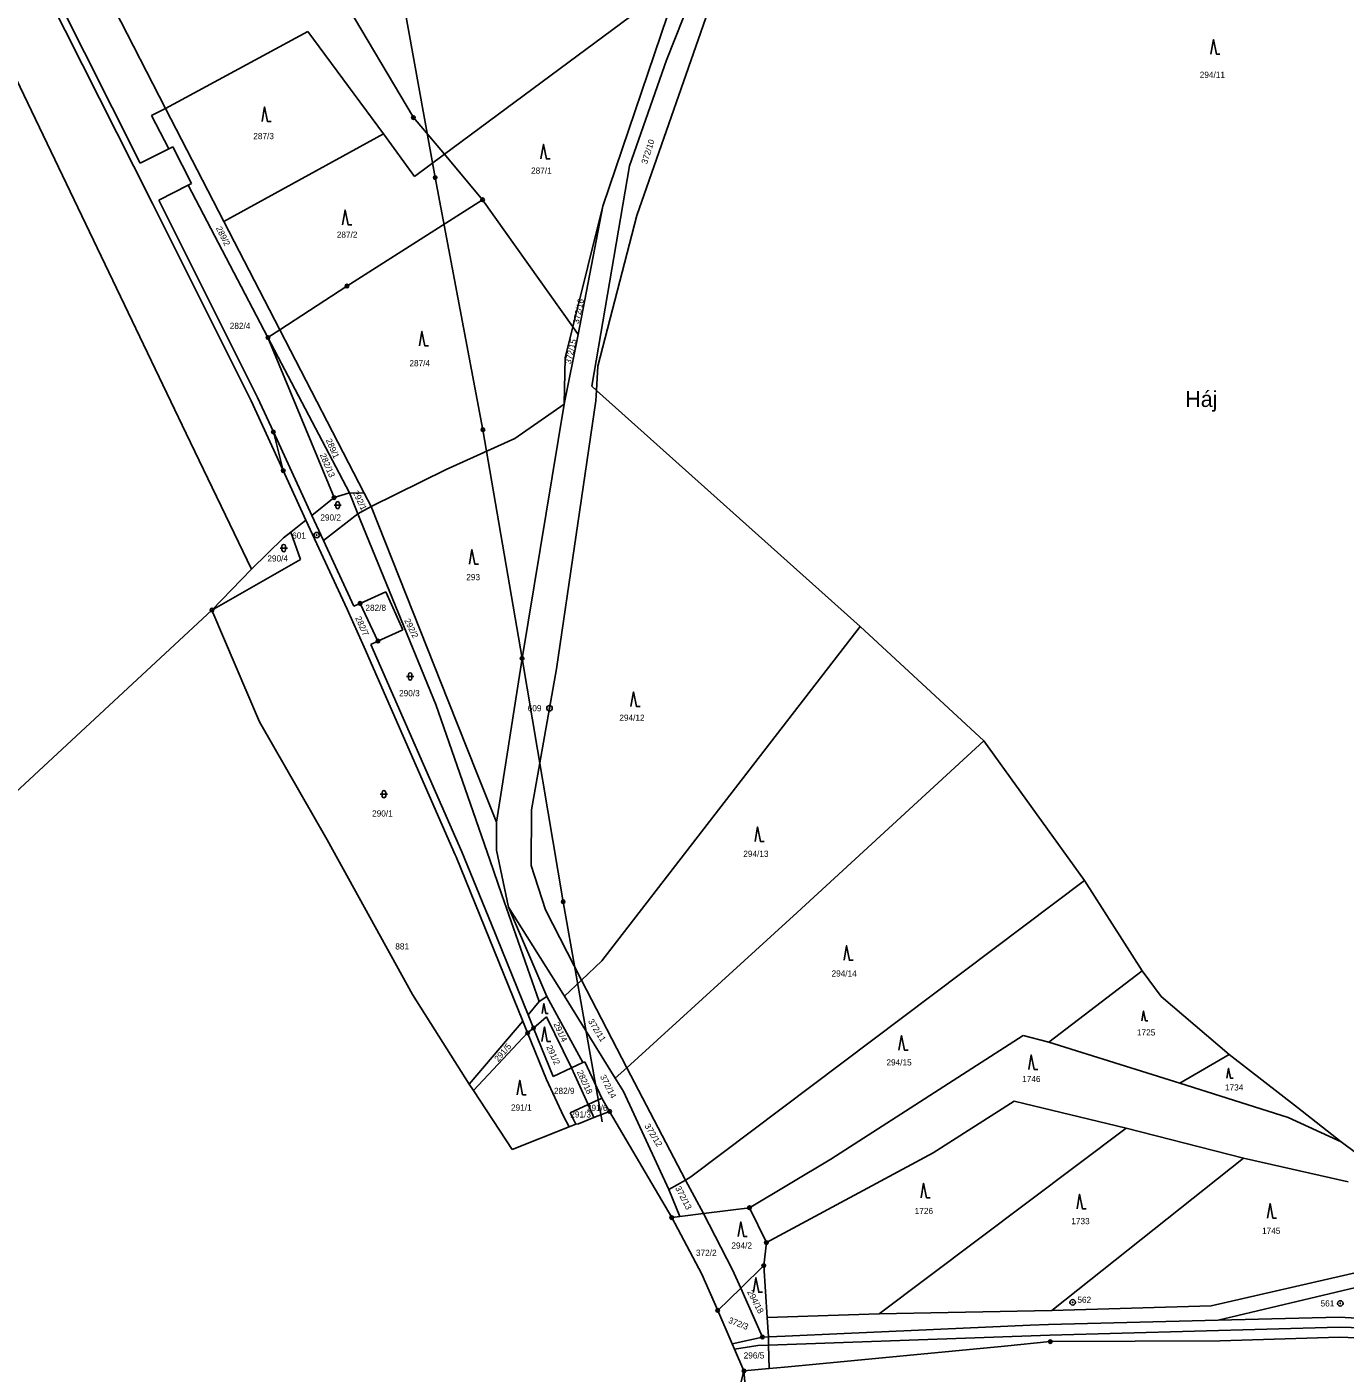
# Model space of a CAD drawing. Extents: x -762263 to -760336, y -1154405 to -1152076.
# Drawn here: x -761653.2 to -761289.6, y -1153689.1 to -1153317.8 of the extents above; entities that cross this region are included whole.
import ezdxf

# ---------------------------------------------------------------- set-up
doc = ezdxf.new("R2010")
doc.units = 0
for name, color, linetype in [('Vrstva 1', 7, 'Continuous'), ('Vrstva 10', 7, 'Continuous'), ('Vrstva 12', 7, 'Continuous'), ('Vrstva 13', 7, 'Continuous'), ('Vrstva 15', 7, 'Continuous'), ('Vrstva 17', 7, 'Continuous'), ('Vrstva 18', 7, 'Continuous'), ('Vrstva 24', 7, 'Continuous'), ('Vrstva 25', 7, 'Continuous'), ('Vrstva 26', 7, 'Continuous'), ('Vrstva 6', 7, 'Continuous')]:
    doc.layers.add(name, color=color, linetype=linetype)

msp = doc.modelspace()

# ---------------------------------------------------------------- linework, layer by layer
at = {"layer": 'Vrstva 1'}
for p, q in [((-761546.59, -1153342.78), (-761585.96, -1153276.37)), ((-761671.74, -1153299.75), (-761609.26, -1153429.89)), ((-761623.76, -1153356.3), (-761651.47, -1153301.16)), ((-761649.68, -1153300.26), (-761621.98, -1153355.4)), ((-761615.01, -1153340.25), (-761634.02, -1153303.16)), ((-761538.06, -1153352.92), (-761473.17, -1153304.68)), ((-761473.17, -1153304.68), (-761494.36, -1153367.21)), ((-761463.8, -1153309.13), (-761484.99, -1153369.81)), ((-761615.01, -1153340.25), (-761575.68, -1153319.01)), ((-761575.68, -1153319.01), (-761554.88, -1153347.32)), ((-761615.01, -1153340.25), (-761618.84, -1153342.23)), ((-761598.9, -1153371.41), (-761615.01, -1153340.25)), ((-761618.84, -1153342.23), (-761614.04, -1153351.37)), ((-761546.59, -1153342.78), (-761538.06, -1153352.92)), ((-761554.88, -1153347.32), (-761598.9, -1153371.41)), ((-761554.88, -1153347.32), (-761546.28, -1153359.03)), ((-761621.98, -1153355.4), (-761614.04, -1153351.37)), ((-761614.04, -1153351.37), (-761612.97, -1153350.83)), ((-761612.97, -1153350.83), (-761607.81, -1153361)), ((-761546.28, -1153359.03), (-761538.06, -1153352.92)), ((-761527.52, -1153365.45), (-761538.06, -1153352.92)), ((-761618.61, -1153366.47), (-761623.76, -1153356.3)), ((-761608.74, -1153361.47), (-761616.82, -1153365.57)), ((-761607.81, -1153361), (-761608.74, -1153361.47)), ((-761608.74, -1153361.47), (-761586.71, -1153403.45)), ((-761616.82, -1153365.57), (-761589.59, -1153420.02)), ((-761527.52, -1153365.45), (-761564.95, -1153389.27)), ((-761591.38, -1153420.92), (-761618.61, -1153366.47)), ((-761502.61, -1153400.49), (-761494.36, -1153367.21)), ((-761484.99, -1153369.81), (-761495.74, -1153411.4)), ((-761583.44, -1153401.32), (-761598.9, -1153371.41)), ((-761564.95, -1153389.27), (-761583.44, -1153401.32)), ((-761583.44, -1153401.32), (-761586.71, -1153403.45)), ((-761586.71, -1153403.45), (-761568.46, -1153447.6)), ((-761586.71, -1153403.45), (-761564.19, -1153446.25)), ((-761560.14, -1153446.41), (-761583.44, -1153401.32)), ((-761504.73, -1153409.05), (-761502.61, -1153400.49)), ((-761504.73, -1153409.05), (-761504.96, -1153421.81)), ((-761495.74, -1153411.4), (-761496.11, -1153418.05)), ((-761496.11, -1153418.05), (-761496.27, -1153420.93)), ((-761582.51, -1153440.17), (-761591.38, -1153420.92)), ((-761589.59, -1153420.02), (-761585.22, -1153429.51)), ((-761504.96, -1153421.81), (-761518.6, -1153431.34)), ((-761504.96, -1153421.81), (-761516.6, -1153491.95)), ((-761496.27, -1153420.93), (-761507.12, -1153494.8)), ((-761585.22, -1153429.51), (-761582.51, -1153440.17)), ((-761574.62, -1153452.51), (-761585.22, -1153429.51)), ((-761609.26, -1153429.89), (-761591.28, -1153467.34)), ((-761537.59, -1153439.84), (-761518.6, -1153431.34)), ((-761576.23, -1153453.8), (-761582.51, -1153440.17)), ((-761558.26, -1153450.05), (-761537.59, -1153439.84)), ((-761568.46, -1153447.6), (-761574.62, -1153452.51)), ((-761568.46, -1153447.6), (-761564.19, -1153446.25)), ((-761560.14, -1153446.41), (-761564.19, -1153446.25)), ((-761564.19, -1153446.25), (-761561.91, -1153452.09)), ((-761558.26, -1153450.05), (-761560.14, -1153446.41)), ((-761536.98, -1153503.67), (-761558.26, -1153450.05)), ((-761580.38, -1153457.11), (-761576.23, -1153453.8)), ((-761564.89, -1153478.4), (-761576.23, -1153453.8)), ((-761571.44, -1153459.41), (-761574.62, -1153452.51)), ((-761561.91, -1153452.09), (-761561.2, -1153453.92)), ((-761561.2, -1153453.92), (-761540.45, -1153504.69)), ((-761591.28, -1153467.34), (-761582.39, -1153458.71)), ((-761582.39, -1153458.71), (-761580.38, -1153457.11)), ((-761563.07, -1153477.59), (-761571.44, -1153459.41)), ((-761591.28, -1153467.34), (-761602.19, -1153478.64)), ((-761554.21, -1153473.62), (-761561.31, -1153476.8)), ((-761549.51, -1153484.11), (-761554.21, -1153473.62)), ((-761563.07, -1153477.59), (-761561.31, -1153476.8)), ((-761561.31, -1153476.8), (-761556.38, -1153487.19)), ((-761560.19, -1153488.9), (-761564.89, -1153478.4)), ((-761556.38, -1153487.19), (-761549.51, -1153484.11)), ((-761560.19, -1153488.9), (-761535.03, -1153546.15)), ((-761556.38, -1153487.19), (-761558.36, -1153488.08)), ((-761558.36, -1153488.08), (-761533.2, -1153545.34)), ((-761523.68, -1153537.15), (-761516.6, -1153491.95)), ((-761514.01, -1153533.68), (-761507.12, -1153494.8)), ((-761536.98, -1153503.67), (-761528.98, -1153523.8)), ((-761540.45, -1153504.69), (-761530.88, -1153532.15)), ((-761528.98, -1153523.8), (-761523.68, -1153537.15)), ((-761530.88, -1153532.15), (-761525.53, -1153547.5)), ((-761523.68, -1153537.15), (-761523.7, -1153544.89)), ((-761514.11, -1153549.12), (-761514.01, -1153533.68)), ((-761535.03, -1153546.15), (-761534.83, -1153546.64)), ((-761534.83, -1153546.64), (-761516.39, -1153592.04)), ((-761525.18, -1153565.08), (-761533.2, -1153545.34)), ((-761525.53, -1153547.5), (-761522.16, -1153557.16)), ((-761520.35, -1153560.57), (-761523.7, -1153544.89)), ((-761510.2, -1153561.34), (-761514.11, -1153549.12)), ((-761522.16, -1153557.16), (-761511.91, -1153586.55)), ((-761509.76, -1153585.2), (-761520.35, -1153560.57)), ((-761510.2, -1153561.34), (-761500.2, -1153580.68)), ((-761514.93, -1153590.3), (-761525.18, -1153565.08)), ((-761500.2, -1153580.68), (-761487.71, -1153604.85)), ((-761511.91, -1153586.55), (-761509.76, -1153585.2)), ((-761509.76, -1153585.2), (-761499.82, -1153603.44)), ((-761514.93, -1153590.3), (-761511.91, -1153586.55)), ((-761531.17, -1153609.36), (-761516.39, -1153592.04)), ((-761515.08, -1153595.26), (-761516.39, -1153592.04)), ((-761513.46, -1153593.93), (-761514.93, -1153590.3)), ((-761515.08, -1153595.26), (-761513.46, -1153593.93)), ((-761515.08, -1153595.26), (-761509.86, -1153608.11)), ((-761513.46, -1153593.93), (-761508.04, -1153607.27)), ((-761502.98, -1153604.91), (-761499.82, -1153603.44)), ((-761499.82, -1153603.44), (-761499.34, -1153603.22)), ((-761494.66, -1153613.28), (-761499.34, -1153603.22)), ((-761508.04, -1153607.27), (-761502.98, -1153604.91)), ((-761487.71, -1153604.85), (-761471.51, -1153635.83)), ((-761509.86, -1153608.11), (-761505.18, -1153618.17)), ((-761503.36, -1153617.33), (-761498.42, -1153615.03)), ((-761498.42, -1153615.03), (-761494.66, -1153613.28)), ((-761494.66, -1153613.28), (-761492.48, -1153616.91)), ((-761505.18, -1153618.17), (-761503.66, -1153621.12)), ((-761501.77, -1153620.41), (-761503.36, -1153617.33)), ((-761471.51, -1153635.83), (-761466.61, -1153645.08)), ((-761453.91, -1153643.47), (-761466.61, -1153645.08)), ((-761449.22, -1153653.1), (-761453.91, -1153643.47)), ((-761473.07, -1153645.89), (-761475.33, -1153646.18)), ((-761466.61, -1153645.08), (-761473.07, -1153645.89)), ((-761466.61, -1153645.08), (-761458.55, -1153660.55)), ((-761449.94, -1153659.44), (-761449.22, -1153653.1)), ((-761456.3, -1153665.62), (-761449.94, -1153659.44)), ((-761456.3, -1153665.62), (-761458.55, -1153660.55)), ((-761462.66, -1153671.8), (-761456.3, -1153665.62)), ((-761456.3, -1153665.62), (-761450.3, -1153679.16)), ((-761371.36, -1153675.66), (-761324.64, -1153674.46)), ((-761324.64, -1153674.46), (-761291.26, -1153673.61)), ((-761291.26, -1153673.61), (-761275.44, -1153674.5)), ((-761427.75, -1153678.16), (-761444.01, -1153678.88)), ((-761376.47, -1153675.89), (-761427.75, -1153678.16)), ((-761371.36, -1153675.66), (-761376.47, -1153675.89)), ((-761450.3, -1153679.16), (-761458.67, -1153680.99)), ((-761448.66, -1153679.09), (-761450.3, -1153679.16)), ((-761444.01, -1153678.88), (-761448.66, -1153679.09)), ((-761448.66, -1153679.09), (-761448.61, -1153681.37)), ((-761448.61, -1153681.37), (-761448.46, -1153687.82)), ((-761439.34, -1153686.94), (-761383.57, -1153681.61)), ((-761383.57, -1153681.61), (-761370.9, -1153680.4)), ((-761324.05, -1153680.22), (-761370.9, -1153680.4)), ((-761291.2, -1153679.17), (-761324.05, -1153680.22)), ((-761291.2, -1153679.17), (-761277.28, -1153679.74)), ((-761448.46, -1153687.82), (-761455.41, -1153688.48)), ((-761455.41, -1153688.48), (-761454.42, -1153699.45)), ((-761448.46, -1153687.82), (-761444.27, -1153687.41)), ((-761444.27, -1153687.41), (-761439.34, -1153686.94))]:
    msp.add_line(p, q, dxfattribs=at)
at = {"layer": 'Vrstva 10'}
for p, q in [((-761291.23, -1153676.37), (-761371.07, -1153678.63)), ((-761276.25, -1153676.81), (-761291.23, -1153676.37)), ((-761451.57, -1153681.47), (-761458.03, -1153682.46)), ((-761448.61, -1153681.37), (-761451.57, -1153681.47)), ((-761371.07, -1153678.63), (-761448.61, -1153681.37))]:
    msp.add_line(p, q, dxfattribs=at)
at = {"layer": 'Vrstva 12'}
for p, q in [((-761540.59, -1153359.34), (-761554.96, -1153280.07)), ((-761527.43, -1153428.89), (-761540.59, -1153359.34)), ((-761516.6, -1153491.95), (-761527.43, -1153428.89)), ((-761505.28, -1153559.08), (-761516.6, -1153491.95)), ((-761505.28, -1153559.08), (-761494.49, -1153619.73))]:
    msp.add_line(p, q, dxfattribs=at)
at = {"layer": 'Vrstva 13'}
for p, q in [((-761784.65, -1153648.01), (-761602.19, -1153478.64)), ((-761602.19, -1153478.64), (-761589.02, -1153509.45)), ((-761589.02, -1153509.45), (-761570.39, -1153541.98)), ((-761570.39, -1153541.98), (-761546.8, -1153584.66)), ((-761546.8, -1153584.66), (-761531.17, -1153609.36)), ((-761531.17, -1153609.36), (-761530.02, -1153611.11)), ((-761530.02, -1153611.11), (-761519.36, -1153627.45)), ((-761501.09, -1153620.29), (-761496.81, -1153618.61)), ((-761496.81, -1153618.61), (-761492.48, -1153616.91)), ((-761492.48, -1153616.91), (-761475.33, -1153646.18)), ((-761519.36, -1153627.45), (-761503.66, -1153621.12)), ((-761503.66, -1153621.12), (-761501.77, -1153620.41)), ((-761501.77, -1153620.41), (-761501.09, -1153620.29)), ((-761475.33, -1153646.18), (-761467.02, -1153661.75)), ((-761467.02, -1153661.75), (-761462.66, -1153671.8)), ((-761462.66, -1153671.8), (-761458.67, -1153680.99)), ((-761458.67, -1153680.99), (-761458.03, -1153682.46)), ((-761458.03, -1153682.46), (-761455.41, -1153688.48)), ((-761458.47, -1153700.93), (-761455.41, -1153688.48))]:
    msp.add_line(p, q, dxfattribs=at)
at = {"layer": 'Vrstva 24'}
for centre, radius in [((-761546.59, -1153342.78), 0.5), ((-761546.59, -1153342.78), 0.1), ((-761527.52, -1153365.45), 0.5), ((-761527.52, -1153365.45), 0.1), ((-761564.95, -1153389.27), 0.5), ((-761564.95, -1153389.27), 0.1), ((-761586.71, -1153403.45), 0.5), ((-761586.71, -1153403.45), 0.1), ((-761585.22, -1153429.51), 0.5), ((-761585.22, -1153429.51), 0.1), ((-761582.51, -1153440.17), 0.5), ((-761582.51, -1153440.17), 0.1), ((-761568.46, -1153447.6), 0.5), ((-761568.46, -1153447.6), 0.1), ((-761573.27, -1153457.95), 0.75), ((-761573.27, -1153457.95), 0.1), ((-761561.31, -1153476.8), 0.5), ((-761561.31, -1153476.8), 0.1), ((-761602.19, -1153478.64), 0.5), ((-761602.19, -1153478.64), 0.1), ((-761556.38, -1153487.19), 0.5), ((-761556.38, -1153487.19), 0.1), ((-761509.05, -1153505.69), 0.75), ((-761509.05, -1153505.69), 0.1), ((-761515.08, -1153595.26), 0.5), ((-761515.08, -1153595.26), 0.1), ((-761513.46, -1153593.93), 0.5), ((-761513.46, -1153593.93), 0.1), ((-761492.48, -1153616.91), 0.5), ((-761492.48, -1153616.91), 0.1), ((-761453.91, -1153643.47), 0.5), ((-761453.91, -1153643.47), 0.1), ((-761475.33, -1153646.18), 0.5), ((-761475.33, -1153646.18), 0.1), ((-761449.22, -1153653.1), 0.5), ((-761449.22, -1153653.1), 0.1), ((-761449.94, -1153659.44), 0.5), ((-761449.94, -1153659.44), 0.1), ((-761364.72, -1153669.57), 0.75), ((-761364.72, -1153669.57), 0.1), ((-761290.9, -1153669.85), 0.75), ((-761290.9, -1153669.85), 0.1), ((-761462.66, -1153671.8), 0.5), ((-761462.66, -1153671.8), 0.1), ((-761450.3, -1153679.16), 0.5), ((-761450.3, -1153679.16), 0.1), ((-761370.9, -1153680.4), 0.5), ((-761370.9, -1153680.4), 0.1), ((-761455.41, -1153688.48), 0.5), ((-761455.41, -1153688.48), 0.1)]:
    msp.add_circle(centre, radius, dxfattribs=at)
at = {"layer": 'Vrstva 25'}
for p, q in [((-761568.48, -1153449.69), (-761566.48, -1153449.69)), ((-761567.98, -1153450.19), (-761567.98, -1153449.19)), ((-761566.98, -1153449.19), (-761566.98, -1153450.19)), ((-761583.36, -1153461.53), (-761581.36, -1153461.53)), ((-761582.86, -1153462.03), (-761582.86, -1153461.03)), ((-761581.86, -1153461.03), (-761581.86, -1153462.03)), ((-761548.49, -1153496.92), (-761546.49, -1153496.92)), ((-761547.99, -1153497.42), (-761547.99, -1153496.42)), ((-761546.99, -1153496.42), (-761546.99, -1153497.42)), ((-761555.72, -1153529.41), (-761553.72, -1153529.41)), ((-761555.22, -1153529.91), (-761555.22, -1153528.91)), ((-761554.22, -1153528.91), (-761554.22, -1153529.91))]:
    msp.add_line(p, q, dxfattribs=at)
for points in [[(-761326.6, -1153325.27), (-761325.9, -1153321.27), (-761325.1, -1153325.27), (-761324.1, -1153325.27)], [(-761588.35, -1153343.83), (-761587.65, -1153339.83), (-761586.85, -1153343.83), (-761585.85, -1153343.83)], [(-761511.4, -1153354.2), (-761510.7, -1153350.2), (-761509.9, -1153354.2), (-761508.9, -1153354.2)], [(-761566.12, -1153372.33), (-761565.42, -1153368.33), (-761564.62, -1153372.33), (-761563.62, -1153372.33)], [(-761544.93, -1153405.78), (-761544.23, -1153401.78), (-761543.43, -1153405.78), (-761542.43, -1153405.78)], [(-761531.15, -1153465.95), (-761530.45, -1153461.95), (-761529.65, -1153465.95), (-761528.65, -1153465.95)], [(-761486.57, -1153505.22), (-761485.87, -1153501.22), (-761485.07, -1153505.22), (-761484.07, -1153505.22)], [(-761452.36, -1153542.44), (-761451.66, -1153538.44), (-761450.86, -1153542.44), (-761449.86, -1153542.44)], [(-761427.81, -1153575.22), (-761427.11, -1153571.22), (-761426.31, -1153575.22), (-761425.31, -1153575.22)], [(-761511.069, -1153589.85), (-761510.6, -1153587.17), (-761510.064, -1153589.85), (-761509.394, -1153589.85)], [(-761345.639, -1153591.9), (-761345.17, -1153589.22), (-761344.634, -1153591.9), (-761343.964, -1153591.9)], [(-761511.17, -1153597.61), (-761510.47, -1153593.61), (-761509.67, -1153597.61), (-761508.67, -1153597.61)], [(-761412.64, -1153599.98), (-761411.94, -1153595.98), (-761411.14, -1153599.98), (-761410.14, -1153599.98)], [(-761376.85, -1153605.32), (-761376.15, -1153601.32), (-761375.35, -1153605.32), (-761374.35, -1153605.32)], [(-761322.169, -1153607.74), (-761321.7, -1153605.06), (-761321.164, -1153607.74), (-761320.494, -1153607.74)], [(-761517.98, -1153612.3), (-761517.28, -1153608.3), (-761516.48, -1153612.3), (-761515.48, -1153612.3)], [(-761406.54, -1153640.72), (-761405.84, -1153636.72), (-761405.04, -1153640.72), (-761404.04, -1153640.72)], [(-761363.52, -1153643.75), (-761362.82, -1153639.75), (-761362.02, -1153643.75), (-761361.02, -1153643.75)], [(-761310.99, -1153646.3), (-761310.29, -1153642.3), (-761309.49, -1153646.3), (-761308.49, -1153646.3)], [(-761456.98, -1153651.36), (-761456.28, -1153647.36), (-761455.48, -1153651.36), (-761454.48, -1153651.36)], [(-761452.82, -1153666.77), (-761452.12, -1153662.77), (-761451.32, -1153666.77), (-761450.32, -1153666.77)]]:
    msp.add_lwpolyline(points, dxfattribs=at)
for centre, start, end in [((-761567.48, -1153449.19), 0, 180), ((-761567.48, -1153450.19), 180, 0), ((-761582.36, -1153461.03), 0, 180), ((-761582.36, -1153462.03), 180, 0), ((-761547.49, -1153496.42), 0, 180), ((-761547.49, -1153497.42), 180, 0), ((-761554.72, -1153528.91), 0, 180), ((-761554.72, -1153529.91), 180, 0)]:
    msp.add_arc(centre, 0.5, start, end, dxfattribs=at)
at = {"layer": 'Vrstva 26'}
for centre in [(-761540.59, -1153359.34), (-761527.43, -1153428.89), (-761516.6, -1153491.95), (-761505.28, -1153559.08)]:
    msp.add_circle(centre, 0.5, dxfattribs=at)
at = {"layer": 'Vrstva 6'}
for p, q in [((-761454.55, -1153270.14), (-761476.76, -1153326.98)), ((-761476.76, -1153326.98), (-761486.97, -1153356.08)), ((-761486.97, -1153356.08), (-761497.41, -1153416.9)), ((-761527.52, -1153365.45), (-761502.61, -1153400.49)), ((-761501.11, -1153402.6), (-761494.36, -1153367.21)), ((-761504.96, -1153421.81), (-761501.11, -1153402.6)), ((-761502.61, -1153400.49), (-761501.11, -1153402.6)), ((-761497.41, -1153416.9), (-761496.11, -1153418.05)), ((-761496.11, -1153418.05), (-761423.33, -1153483.2)), ((-761558.26, -1153450.05), (-761561.91, -1153452.09)), ((-761561.91, -1153452.09), (-761571.44, -1153459.41)), ((-761577.72, -1153464.7), (-761580.38, -1153457.11)), ((-761602.19, -1153478.64), (-761577.72, -1153464.7)), ((-761423.33, -1153483.2), (-761494.6, -1153575.41)), ((-761423.33, -1153483.2), (-761389.25, -1153514.7)), ((-761440.72, -1153562.07), (-761389.25, -1153514.7)), ((-761389.25, -1153514.7), (-761361.48, -1153553.17)), ((-761361.48, -1153553.17), (-761470.06, -1153634.97)), ((-761345.6, -1153578.17), (-761361.48, -1153553.17)), ((-761520.35, -1153560.57), (-761504.92, -1153585.11)), ((-761487.71, -1153604.85), (-761440.72, -1153562.07)), ((-761500.2, -1153580.68), (-761494.6, -1153575.41)), ((-761504.92, -1153585.11), (-761500.2, -1153580.68)), ((-761371.27, -1153597.84), (-761345.6, -1153578.17)), ((-761345.6, -1153578.17), (-761340.33, -1153585.2)), ((-761504.92, -1153585.11), (-761490.9, -1153607.7)), ((-761321.57, -1153601.24), (-761340.33, -1153585.2)), ((-761509.84, -1153590.84), (-761513.46, -1153593.93)), ((-761509.84, -1153590.84), (-761502.98, -1153604.91)), ((-761530.02, -1153611.11), (-761515.08, -1153595.26)), ((-761431.4, -1153630.03), (-761378.43, -1153595.99)), ((-761378.43, -1153595.99), (-761371.27, -1153597.84)), ((-761371.27, -1153597.84), (-761335.2, -1153609.08)), ((-761335.2, -1153609.08), (-761321.57, -1153601.24)), ((-761321.57, -1153601.24), (-761302.69, -1153615.85)), ((-761502.98, -1153604.91), (-761498.42, -1153615.03)), ((-761490.9, -1153607.7), (-761487.71, -1153604.85)), ((-761490.9, -1153607.7), (-761488.65, -1153611.4)), ((-761488.65, -1153611.4), (-761476.1, -1153638.45)), ((-761335.2, -1153609.08), (-761305.31, -1153618.62)), ((-761498.42, -1153615.03), (-761496.81, -1153618.61)), ((-761403.24, -1153628.3), (-761380.87, -1153614.08)), ((-761380.87, -1153614.08), (-761349.98, -1153621.56)), ((-761305.31, -1153618.62), (-761290.69, -1153625.31)), ((-761302.69, -1153615.85), (-761290.69, -1153625.31)), ((-761418.13, -1153672.7), (-761349.98, -1153621.56)), ((-761349.98, -1153621.56), (-761317.63, -1153629.8)), ((-761290.69, -1153625.31), (-761282.41, -1153631.47)), ((-761453.91, -1153643.47), (-761431.4, -1153630.03)), ((-761449.22, -1153653.1), (-761403.24, -1153628.3)), ((-761370.5, -1153671.81), (-761317.63, -1153629.8)), ((-761317.63, -1153629.8), (-761288.72, -1153636.31)), ((-761471.51, -1153635.83), (-761476.1, -1153638.45)), ((-761470.06, -1153634.97), (-761471.51, -1153635.83)), ((-761476.1, -1153638.45), (-761473.07, -1153645.89)), ((-761449.94, -1153659.44), (-761449.01, -1153673.74)), ((-761326.5, -1153670.48), (-761266.86, -1153656.88)), ((-761324.64, -1153674.46), (-761263.67, -1153660)), ((-761370.5, -1153671.81), (-761326.5, -1153670.48)), ((-761449.01, -1153673.74), (-761418.13, -1153672.7)), ((-761449.01, -1153673.74), (-761448.66, -1153679.09)), ((-761418.13, -1153672.7), (-761370.5, -1153671.81))]:
    msp.add_line(p, q, dxfattribs=at)

# ---------------------------------------------------------------- texts
at = {"layer": 'Vrstva 15'}
msp.add_text('Háj', height=4.4, dxfattribs=at).set_placement((-761333.642, -1153422.61))
at = {"layer": 'Vrstva 17'}
for s, p in [('601', (-761580.033, -1153458.92)), ('609', (-761515.058, -1153506.54)), ('881', (-761551.592, -1153572.24)), ('562', (-761363.427, -1153669.7)), ('561', (-761296.346, -1153670.7))]:
    msp.add_text(s, height=1.7, dxfattribs=at).set_placement(p)
at = {"layer": 'Vrstva 18'}
for s, p in [('294/11', (-761329.67, -1153331.84)), ('287/3', (-761590.763, -1153348.75)), ('287/1', (-761514.135, -1153358.27)), ('287/2', (-761567.733, -1153375.94)), ('282/4', (-761597.253, -1153401.09)), ('287/4', (-761547.693, -1153411.4)), ('290/2', (-761572.257, -1153453.94)), ('290/4', (-761586.874, -1153465.23)), ('293', (-761532.003, -1153470.39)), ('282/8', (-761559.827, -1153478.84)), ('290/3', (-761550.541, -1153502.4)), ('294/12', (-761489.782, -1153509.16)), ('290/1', (-761557.986, -1153535.57)), ('294/13', (-761455.585, -1153546.69)), ('294/14', (-761431.248, -1153579.71)), ('1725', (-761346.996, -1153595.96)), ('294/15', (-761416.105, -1153604.23)), ('1746', (-761378.655, -1153608.81)), ('282/9', (-761507.827, -1153612.09)), ('1734', (-761322.702, -1153611.13)), ('291/1', (-761519.671, -1153616.68)), ('291/6', (-761498.739, -1153616.77)), ('291/3', (-761503.306, -1153618.58)), ('1726', (-761408.309, -1153645.21)), ('1733', (-761365.099, -1153648)), ('1745', (-761312.482, -1153650.67)), ('372/2', (-761468.643, -1153656.74)), ('294/2', (-761458.873, -1153654.74)), ('296/5', (-761455.483, -1153685.05))]:
    msp.add_text(s, height=1.7, dxfattribs=at).set_placement(p)
for s, rotation, p in [('372/10', 72.47916, (-761482.131, -1153355.75)), ('289/2', 296.56296, (-761601.124, -1153373.312)), ('372/16', 78.03685, (-761500.967, -1153399.79)), ('372/15', 76.77634, (-761503.172, -1153410.887)), ('289/1', 293.81276, (-761570.796, -1153431.776)), ('282/13', 292.95332, (-761572.427, -1153435.839)), ('292/1', 295.18786, (-761563.336, -1153446.165)), ('282/7', 293.92735, (-761562.674, -1153480.807)), ('292/2', 296.56296, (-761549.174, -1153481.492)), ('291/4', 294.95867, (-761508.003, -1153592.786)), ('372/11', 302.00605, (-761498.5, -1153592.022)), ('291/5', 48.70141, (-761523.186, -1153603.328)), ('291/2', 294.72949, (-761509.982, -1153599.114)), ('282/18', 294.95867, (-761501.555, -1153606.022)), ('372/14', 296.73484, (-761495.152, -1153607.301)), ('372/12', 301.26121, (-761482.899, -1153620.908)), ('372/13', 297.53698, (-761474.431, -1153638.039)), ('294/18', 297.76617, (-761454.582, -1153666.687)), ('372/3', 338.73265, (-761459.893, -1153675.149))]:
    msp.add_text(s, height=1.7, rotation=rotation, dxfattribs=at).set_placement(p)

doc.saveas('drawing.dxf')
